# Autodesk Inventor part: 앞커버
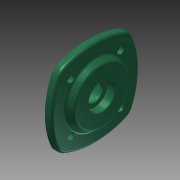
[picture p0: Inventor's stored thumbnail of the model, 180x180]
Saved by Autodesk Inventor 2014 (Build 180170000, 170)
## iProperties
Created: 2015-11
Part Number: 앞커버
Material: Aluminum 6061
Document SubType Name: Modeling
Designer: mduedu
Density: 2.71 g/cm^3
Mass: 305.846 g
Surface Area: 251.177 cm^2
Volume: 112.858 cm^3
Appearance: Smooth - Dark Sea Green
Author: mduedu
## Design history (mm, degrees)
sketch "스케치1"
  geometry: L1 (50, 50)-(-50, 50); L2 (-50, 50)-(-50, -50); L3 (-50, -50)-(50, -50); L4 (50, -50)-(50, 50); L5 (0, 50)-(0, -50); L6 (50, 0)-(-50, 0); A1 r 90 centre (-40, 0) between (40.415, -40.415) and (40.415, 40.415); A2 r 90 centre (40, 0) between (-40.415, 40.415) and (-40.415, -40.415); A3 r 90 centre (0, -40) between (40.415, 40.415) and (-40.415, 40.415); A4 r 90 centre (0, 40) between (-40.415, -40.415) and (40.415, -40.415); 2 further points
  constraints: 12 end point, 8 point on circle, 5 midpoint, 4 centre point, 2 horizontal alignment, 2 parallel, 2 perpendicular, 2 symmetric about line, 2 tangent, 2 vertical alignment, 1 equal radius, 1 horizontal, 2 other
  dimensions: "d0" = 100 distance of L3.end L1.start; "d2" = 90 radius of A1
extrude "돌출1" new body sketch "스케치1" distance "d3" = 8; taper "d4" = 0 deg
sketch "스케치2"
  geometry: C1 r 35 at (0, 0); 1 further point
  constraints: 1 centre point, 1 coincident
  dimensions: "d5" = 70 diameter of C1
extrude "돌출2" join sketch "스케치2" distance "d6" = 7; taper "d7" = -30 deg
sketch "스케치3"
  geometry: L1 (0, 0)-(0, 40); L2 (0, 0)-(-28.284, 28.284); A1 r 40 centre (0, 0) between (0, 40) and (-28.284, 28.284); 2 further points
  constraints: 4 end point, 2 coincident, 2 point on circle, 1 centre point, 1 vertical
  dimensions: "d8" = 80 diameter of A1; "d9" = 45 deg angle of L1 L2
hole "구멍1" sketch "스케치3" at (-28.284, 28.284) diameter "d11" = 4.5; stored, may be unused: countersink angle "d15" = 90 deg, drill point angle "d17" = 118 deg; dims "d12" = 6, "d13" = 8, "d14" = 4.4, "d16" = 8
sketch "스케치4"
  geometry: C1 r 35 at (0, 0); 1 further point
  constraints: 1 centre point, 1 coincident
  dimensions: "d21" = 70 diameter of C1
extrude "돌출3" join sketch "스케치4" distance "d23" = 12; taper "d24" = 0 deg
hole "구멍2" diameter "d27" = 30; stored, may be unused: countersink angle "d31" = 90 deg, drill point angle "d33" = 0 deg; dims "d25" = 10, "d26" = 10, "d28" = 6, "d29" = 40, "d30" = 12, "d32" = 15
fillet "모깎기2" dims "d35" = 15
fillet "모깎기3" dims "d36" = 3
fillet "모깎기4" dims "d37" = 3
fillet "모깎기5" dims "d38" = 0.3
chamfer "모따기1" distance "d39" = 1; stored, may be unused: second distance "d40" = 2, angle "d41" = 45 deg
hole "구멍3" diameter "d44" = 20; stored, may be unused: countersink angle "d48" = 90 deg, drill point angle "d50" = 118 deg; dims "d45" = 6, "d46" = 30, "d47" = 8.7, "d49" = 8, "d55" = 10, "d56" = 10
fillet "모깎기6" dims "d51" = 0.3
chamfer "모따기2" distance "d52" = 0.7; stored, may be unused: second distance "d53" = 2, angle "d54" = 30 deg
node "솔리드1"
pattern_circular "원형 패턴1" dims angle "d19" = 360 deg
